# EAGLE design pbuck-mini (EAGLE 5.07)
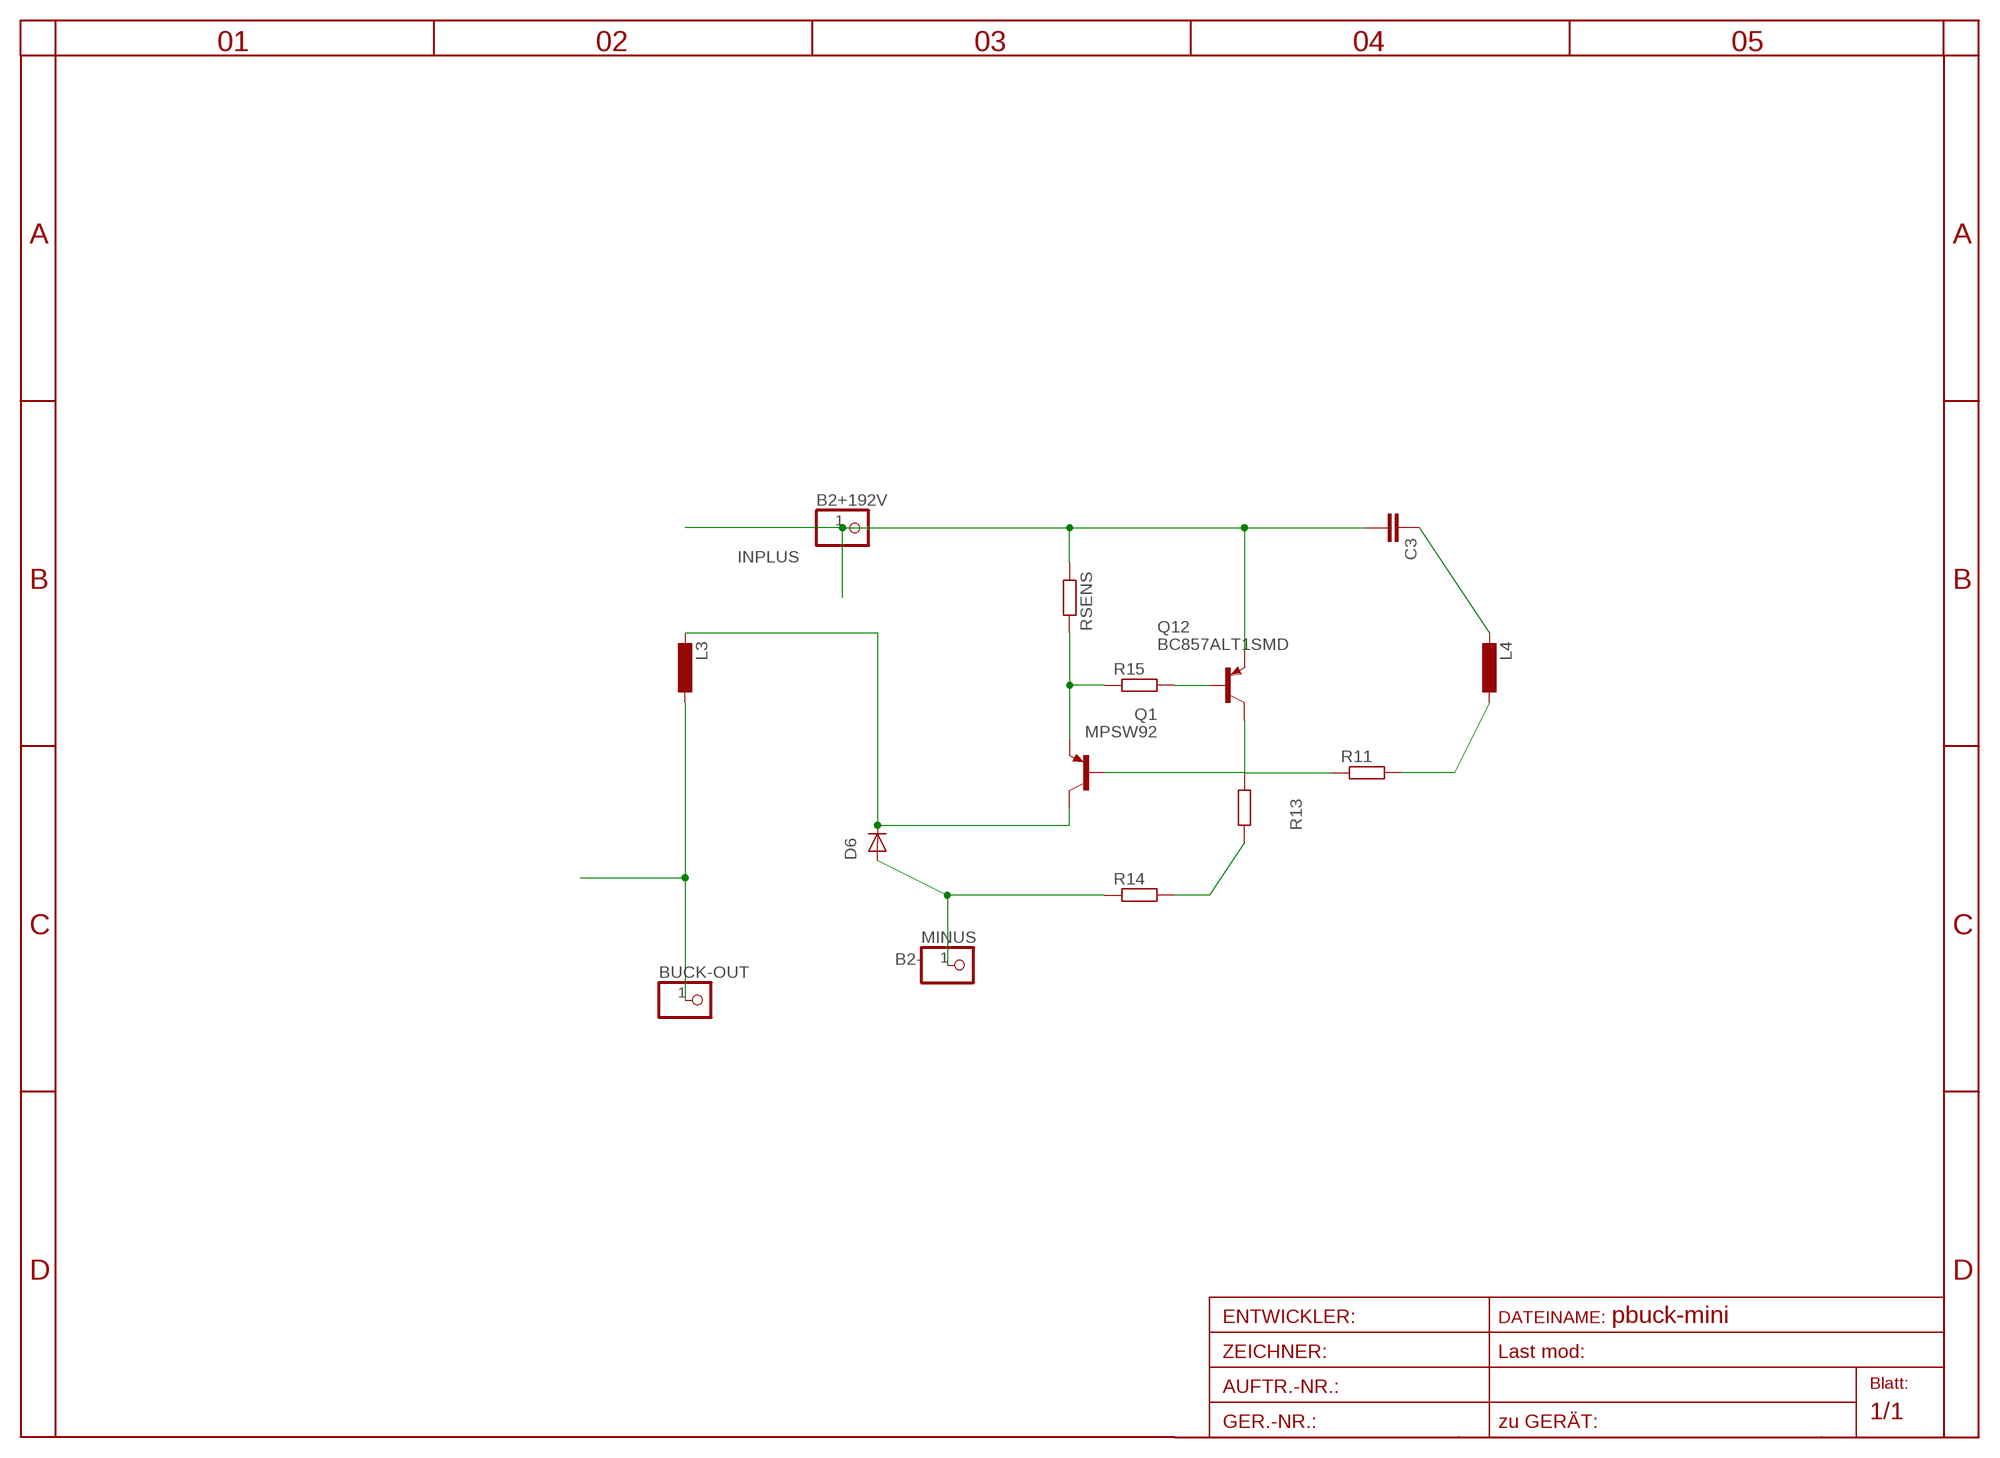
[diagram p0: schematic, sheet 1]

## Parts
B2+192V  PINHD-1X12MM3  [1X2MM3]
BUCK-OUT  PINHD-1X12MM3  [1X2MM3]
C3  C-EUC0805  [C0805]
D6  DIODE-SMA-DO214  [SMA-DO214AC]
L3  L-EU0204/5  [0204/5]
L4  L-EU0204/5  [0204/5]
MINUS  PINHD-1X12MM3  [1X2MM3]
Q1  MPSW92  [TO92-CBE]
Q12  BC857ALT1SMD  [SOT23-BEC]
R11  R-EU_R0805  [R0805]
R13  R-EU_R1206  [R1206]
R14  R-EU_R1206  [R1206]
R15  R-EU_R0805  [R0805]
RSENS  R-EU_R1206  [R1206]

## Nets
B2-: D6.A MINUS.1 R14.1
B92: Q1.B Q12.C R11.1 R13.1
B_OUT: BUCK-OUT.1 L3.1
C92: D6.K(C) L3.2 Q1.C
EB: Q1.E R15.1 RSENS.2
INPLUS: B2+192V.1 C3.2 Q12.E RSENS.1
L4DOT: C3.1 L4.2
L4NO: L4.1 R11.2
N$11: R13.2 R14.2
N$12: Q12.B R15.2

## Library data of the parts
B2+192V BUCK-OUT MINUS = pinhead:PINHD-1X1: PIN HEADER
C3 = rcl:C-EU: CAPACITOR, European symbol
D6 = diode:DIODE-: DIODE
L3 L4 = rcl:L-EU: INDUCTOR, European symbol
Q1 = transistor-pnp:MPSW92*: PNP Transistror
Q12 = transistor-pnp:BC857*: PNP Transistror
R11 R13-R15 RSENS = rcl:R-EU_: RESISTOR, European symbol

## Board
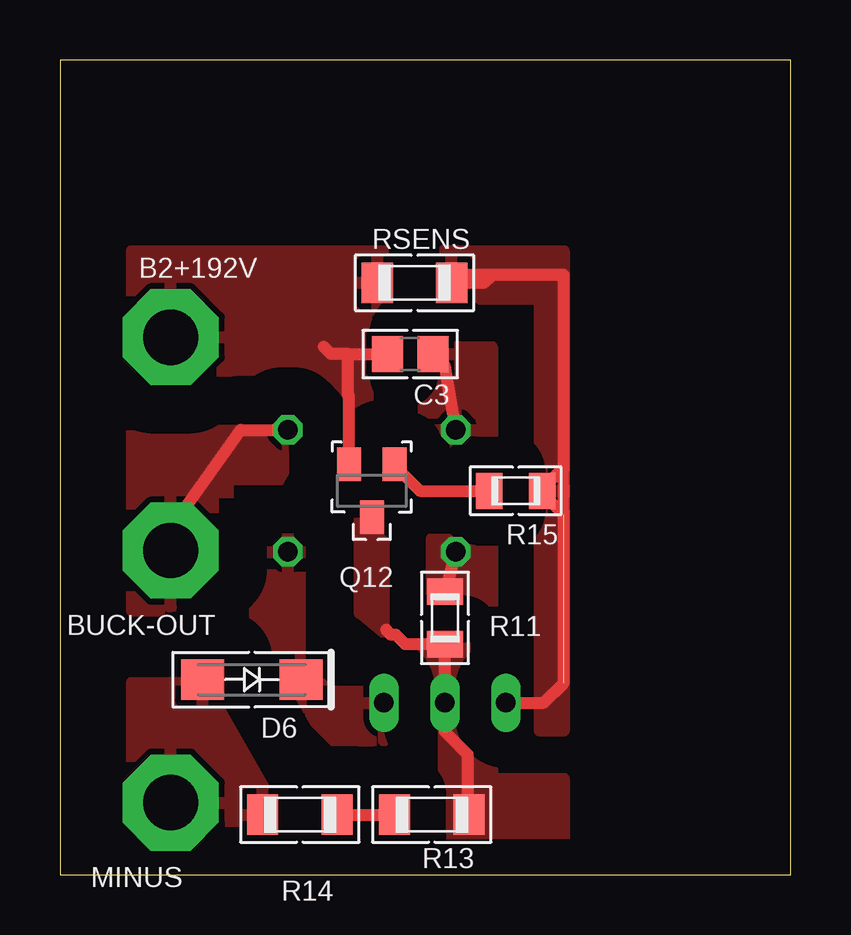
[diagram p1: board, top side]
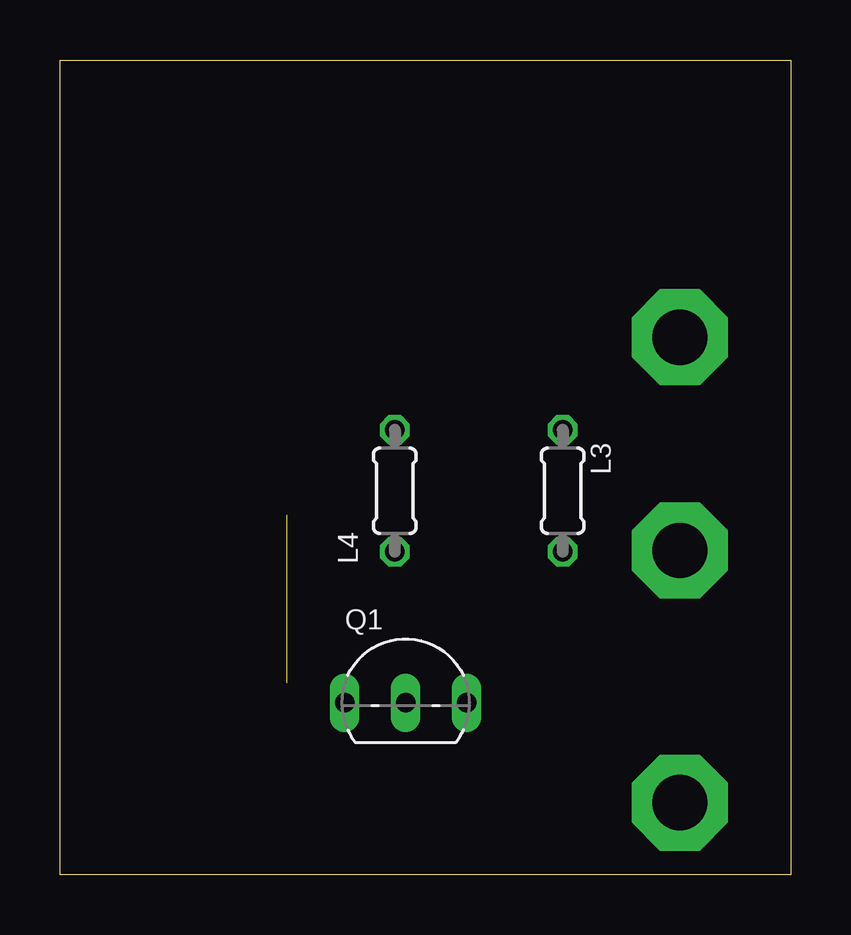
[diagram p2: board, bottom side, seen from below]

Size 30.46 x 33.96 mm. Coordinates in mm from the lower left corner, seen from the top.
Outline: 0,0 30.46,0 30.46,33.96 0,33.96 0,0
Copper layers (1*16): Top 0.035mm / dielectric 1.5mm / Bottom 0.035mm
Design rules "default *": minimum track width 10mil, minimum drill 20mil, track to track 8mil, track to pad 8mil, pad to pad 8mil, via to via 8mil, smd to smd 8mil, copper to edge 40mil, drill to drill 8mil, minimum pad ring 8mil, minimum via ring 8mil, stop-mask expansion 4mil, vias tented up to drill 0mil, thermal gap 10mil

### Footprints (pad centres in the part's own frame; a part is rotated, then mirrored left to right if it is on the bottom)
1X2MM3 = drill 2.3 pad 4 octagon: 1 0,0
C0805 = smd 1.3 x 1.5: 1 -0.95,0; 2 0.95,0
SMA-DO214AC = smd 1.8 x 1.7: A 2.05,-0.127; K -2.05,-0.127
0204/5 = drill 0.813 octagon: 1 -2.54,0; 2 2.54,0
TO92-CBE = drill 0.813 long: B 0,0; C 2.54,0; E -2.54,0
SOT23-BEC = smd 1 x 1.4: B -0.95,-1.1; C 0,1.1; E 0.95,-1.1
R0805 = smd 1.1 x 1.5: 1 -1.1,0; 2 1.1,0
R1206 = smd 1.3 x 1.7: 1 -1.55,0; 2 1.55,0

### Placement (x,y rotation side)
B2+192V  4.62,22.4 0 top
BUCK-OUT  4.62,13.51 0 top
C3  14.6,21.7 180 top
D6  8,8 180 top
L3  9.5,16 270 bottom
L4  16.5,16 90 bottom
MINUS  4.62,3 0 top
Q1  16.05,7.16 0 bottom
Q12  13,16 180 top
R11  16.05,10.7 90 top
R13  15.5,2.5 180 top
R14  10,2.5 0 top
R15  19,16 180 top
RSENS  14.78,24.67 0 top

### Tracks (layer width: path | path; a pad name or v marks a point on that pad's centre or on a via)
B2-
  pour Top (isolate 2, rank 2): 3,8 6,8 10,1 3,1
B92
  Top 0.5: R13.1 17,3.49 17,5 16.05,5.95 Q1.B R11.1 14.4,9.6 14,10 13.8,10 13.6,10.2
  pour Top (isolate 1.5, rank 2, no thermals): 12.5,14.9 18,9 18,4 21,4 21,1 16,1 16,8 12.5,10.9
B_OUT
  Top 0.5: L3.1 7.54,18.54 5,15 5,13.89 BUCK-OUT.1
  pour Top (isolate 2, rank 4): 3,19 10,19 10,18 6,11 3,11
C92
  pour Top (isolate 2, rank 3): 9,14 10,14 10,11 12,9 13,9 15,6 14,5 12,5 9,8 8,11 8,13
EB  (1 unrouted)
  Top 0.5: 18,25 17.67,24.67 RSENS.2 16.66,25 21,25 21,8 20.16,7.16 Q1.E | 21,17 20.1,16.1 R15.1 20.1,15.9 21,15
  pour Top (isolate 1.8): 16,26 21,26 21,6 20,6 20,24 16,24
INPLUS
  Top 0.5: Q12.E 12.05,19.95 12,20 12,21.7 | 12,21.7 11.3,21.7 11,22 | 12,21.7 C3.2
  pour Top (isolate 2): 3,26 14,26 13,17 11,17 11,21 3,21
L4DOT
  Top 0.5: L4.2 16.05,21.2 C3.1
  pour Top (isolate 1.5): 15,22 18,22 18,18 15,18
L4NO
  Top 0.5: L4.1 R11.2
  pour Top (isolate 1.5, no thermals): 15.5,14 18,14 18,11 15.5,11
N$11
  Top 0.5: R14.2 R13.2
N$12
  Top 0.5: Q12.B 13.95,17.05 15,16 R15.2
